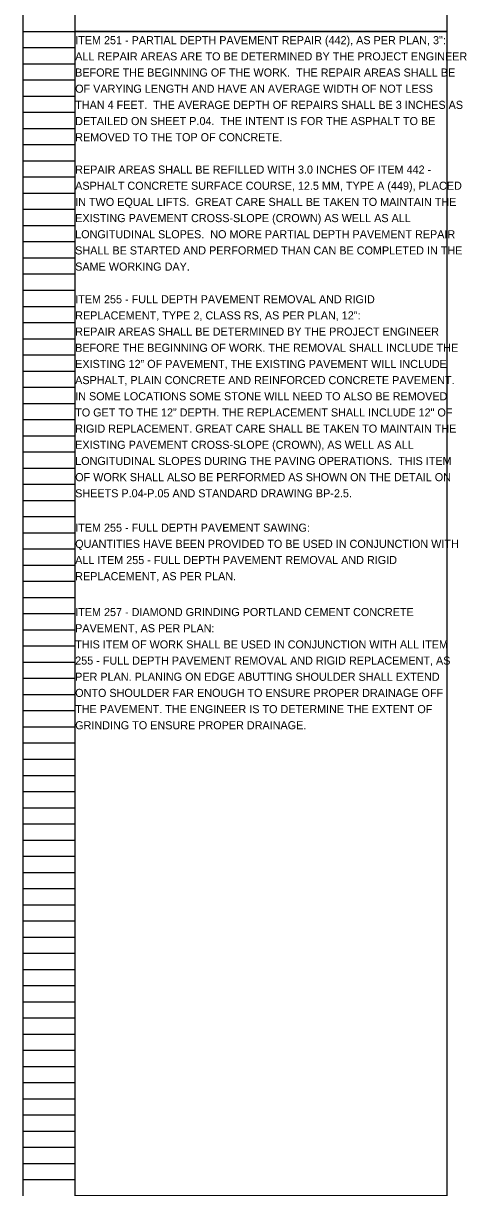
# Model space of a CAD drawing. Extents: x 16463 to 16495, y 5662 to 5823.
# Drawn here: x 16463.05 to 16470.73, y 5783.29 to 5803.45 of the extents above; entities that cross this region are included whole.
import ezdxf

# ---------------------------------------------------------------- set-up
doc = ezdxf.new("R2010")
doc.units = 0
for name, color, linetype in [('Default', 7, 'Continuous'), ('SC_Scratch1', 7, 'Continuous'), ('SH_Data', 7, 'Continuous')]:
    doc.layers.add(name, color=color, linetype=linetype)

msp = doc.modelspace()

# ---------------------------------------------------------------- linework, layer by layer
at = {"layer": 'SC_Scratch1'}
for points in [[(16463.949, 5823.472), (16470.389, 5823.472), (16470.389, 5803.312), (16463.949, 5803.312)], [(16463.949, 5803.312), (16470.389, 5803.312), (16470.389, 5783.152), (16463.949, 5783.152)]]:
    msp.add_lwpolyline(points, close=True, dxfattribs=at)
at = {"layer": 'SH_Data'}
for p, q in [((16463.049, 5803.312), (16463.049, 5823.472)), ((16463.949, 5803.312), (16463.949, 5823.472)), ((16463.049, 5783.152), (16463.049, 5803.312)), ((16463.049, 5803.312), (16463.949, 5803.312)), ((16463.049, 5803.312), (16463.949, 5803.312)), ((16463.949, 5783.152), (16463.949, 5803.312)), ((16463.049, 5803.032), (16463.949, 5803.032)), ((16463.049, 5802.752), (16463.949, 5802.752)), ((16463.049, 5802.472), (16463.949, 5802.472)), ((16463.049, 5802.192), (16463.949, 5802.192)), ((16463.049, 5801.912), (16463.949, 5801.912)), ((16463.049, 5801.632), (16463.949, 5801.632)), ((16463.049, 5801.352), (16463.949, 5801.352)), ((16463.049, 5801.072), (16463.949, 5801.072)), ((16463.049, 5800.792), (16463.949, 5800.792)), ((16463.049, 5800.512), (16463.949, 5800.512)), ((16463.049, 5800.232), (16463.949, 5800.232)), ((16463.049, 5799.952), (16463.949, 5799.952)), ((16463.049, 5799.672), (16463.949, 5799.672)), ((16463.049, 5799.392), (16463.949, 5799.392)), ((16463.049, 5799.112), (16463.949, 5799.112)), ((16463.049, 5798.832), (16463.949, 5798.832)), ((16463.049, 5798.552), (16463.949, 5798.552)), ((16463.049, 5798.272), (16463.949, 5798.272)), ((16463.049, 5797.992), (16463.949, 5797.992)), ((16463.049, 5797.712), (16463.949, 5797.712)), ((16463.049, 5797.432), (16463.949, 5797.432)), ((16463.049, 5797.152), (16463.949, 5797.152)), ((16463.049, 5796.872), (16463.949, 5796.872)), ((16463.049, 5796.592), (16463.949, 5796.592)), ((16463.049, 5796.312), (16463.949, 5796.312)), ((16463.049, 5796.032), (16463.949, 5796.032)), ((16463.049, 5795.752), (16463.949, 5795.752)), ((16463.049, 5795.472), (16463.949, 5795.472)), ((16463.049, 5795.192), (16463.949, 5795.192)), ((16463.049, 5794.912), (16463.949, 5794.912)), ((16463.049, 5794.632), (16463.949, 5794.632)), ((16463.049, 5794.352), (16463.949, 5794.352)), ((16463.049, 5794.072), (16463.949, 5794.072)), ((16463.049, 5793.792), (16463.949, 5793.792)), ((16463.049, 5793.512), (16463.949, 5793.512)), ((16463.049, 5793.232), (16463.949, 5793.232)), ((16463.049, 5792.952), (16463.949, 5792.952)), ((16463.049, 5792.672), (16463.949, 5792.672)), ((16463.049, 5792.392), (16463.949, 5792.392)), ((16463.049, 5792.112), (16463.949, 5792.112)), ((16463.049, 5791.832), (16463.949, 5791.832)), ((16463.049, 5791.552), (16463.949, 5791.552)), ((16463.049, 5791.272), (16463.949, 5791.272)), ((16463.049, 5790.992), (16463.949, 5790.992)), ((16463.049, 5790.712), (16463.949, 5790.712)), ((16463.049, 5790.432), (16463.949, 5790.432)), ((16463.049, 5790.152), (16463.949, 5790.152)), ((16463.049, 5789.872), (16463.949, 5789.872)), ((16463.049, 5789.592), (16463.949, 5789.592)), ((16463.049, 5789.312), (16463.949, 5789.312)), ((16463.049, 5789.032), (16463.949, 5789.032)), ((16463.049, 5788.752), (16463.949, 5788.752)), ((16463.049, 5788.472), (16463.949, 5788.472)), ((16463.049, 5788.192), (16463.949, 5788.192)), ((16463.049, 5787.912), (16463.949, 5787.912)), ((16463.049, 5787.632), (16463.949, 5787.632)), ((16463.049, 5787.352), (16463.949, 5787.352)), ((16463.049, 5787.072), (16463.949, 5787.072)), ((16463.049, 5786.792), (16463.949, 5786.792)), ((16463.049, 5786.512), (16463.949, 5786.512)), ((16463.049, 5786.232), (16463.949, 5786.232)), ((16463.049, 5785.952), (16463.949, 5785.952)), ((16463.049, 5785.672), (16463.949, 5785.672)), ((16463.049, 5785.392), (16463.949, 5785.392)), ((16463.049, 5785.112), (16463.949, 5785.112)), ((16463.049, 5784.832), (16463.949, 5784.832)), ((16463.049, 5784.552), (16463.949, 5784.552)), ((16463.049, 5784.272), (16463.949, 5784.272)), ((16463.049, 5783.992), (16463.949, 5783.992)), ((16463.049, 5783.712), (16463.949, 5783.712)), ((16463.049, 5783.432), (16463.949, 5783.432))]:
    msp.add_line(p, q, dxfattribs=at)

# ---------------------------------------------------------------- texts
at = {"layer": 'Default'}
for s, p in [('ITEM 251 - PARTIAL DEPTH PAVEMENT REPAIR (442), AS PER PLAN, 3":', (16463.949, 5803.09)), ('ALL REPAIR AREAS ARE TO BE DETERMINED BY THE PROJECT ENGINEER ', (16463.949, 5802.81)), ('BEFORE THE BEGINNING OF THE WORK.  THE REPAIR AREAS SHALL BE ', (16463.949, 5802.53)), ('OF VARYING LENGTH AND HAVE AN AVERAGE WIDTH OF NOT LESS ', (16463.949, 5802.25)), ('THAN 4 FEET.  THE AVERAGE DEPTH OF REPAIRS SHALL BE 3 INCHES AS ', (16463.949, 5801.97)), ('DETAILED ON SHEET P.04.  THE INTENT IS FOR THE ASPHALT TO BE ', (16463.949, 5801.69)), ('REMOVED TO THE TOP OF CONCRETE.', (16463.949, 5801.41)), ('REPAIR AREAS SHALL BE REFILLED WITH 3.0 INCHES OF ITEM 442 - ', (16463.949, 5800.85)), ('ASPHALT CONCRETE SURFACE COURSE, 12.5 MM, TYPE A (449), PLACED ', (16463.949, 5800.57)), ('IN TWO EQUAL LIFTS.  GREAT CARE SHALL BE TAKEN TO MAINTAIN THE ', (16463.949, 5800.29)), ('EXISTING PAVEMENT CROSS-SLOPE (CROWN) AS WELL AS ALL ', (16463.949, 5800.01)), ('LONGITUDINAL SLOPES.  NO MORE PARTIAL DEPTH PAVEMENT REPAIR ', (16463.949, 5799.73)), ('SHALL BE STARTED AND PERFORMED THAN CAN BE COMPLETED IN THE ', (16463.949, 5799.45)), ('SAME WORKING DAY.', (16463.949, 5799.17)), ('ITEM 255 - FULL DEPTH PAVEMENT REMOVAL AND RIGID ', (16463.949, 5798.605)), ('REPLACEMENT, TYPE 2, CLASS RS, AS PER PLAN, 12":', (16463.949, 5798.325)), ('REPAIR AREAS SHALL BE DETERMINED BY THE PROJECT ENGINEER ', (16463.949, 5798.045)), ('BEFORE THE BEGINNING OF WORK. THE REMOVAL SHALL INCLUDE THE ', (16463.949, 5797.765)), ('EXISTING 12” OF PAVEMENT, THE EXISTING PAVEMENT WILL INCLUDE ', (16463.949, 5797.485)), ('ASPHALT, PLAIN CONCRETE AND REINFORCED CONCRETE PAVEMENT. ', (16463.949, 5797.205)), ('IN SOME LOCATIONS SOME STONE WILL NEED TO ALSO BE REMOVED ', (16463.949, 5796.925)), ('TO GET TO THE 12” DEPTH. THE REPLACEMENT SHALL INCLUDE 12" OF ', (16463.949, 5796.645)), ('RIGID REPLACEMENT. GREAT CARE SHALL BE TAKEN TO MAINTAIN THE ', (16463.949, 5796.365)), ('EXISTING PAVEMENT CROSS-SLOPE (CROWN), AS WELL AS ALL ', (16463.949, 5796.085)), ('LONGITUDINAL SLOPES DURING THE PAVING OPERATIONS.  THIS ITEM ', (16463.949, 5795.805)), ('OF WORK SHALL ALSO BE PERFORMED AS SHOWN ON THE DETAIL ON ', (16463.949, 5795.525)), ('SHEETS P.04-P.05 AND STANDARD DRAWING BP-2.5.', (16463.949, 5795.245)), ('ITEM 255 - FULL DEPTH PAVEMENT SAWING:', (16463.949, 5794.65)), ('QUANTITIES HAVE BEEN PROVIDED TO BE USED IN CONJUNCTION WITH ', (16463.949, 5794.37)), ('ALL ITEM 255 - FULL DEPTH PAVEMENT REMOVAL AND RIGID ', (16463.949, 5794.09)), ('REPLACEMENT, AS PER PLAN. ', (16463.949, 5793.81)), ('ITEM 257 - DIAMOND GRINDING PORTLAND CEMENT CONCRETE ', (16463.949, 5793.189)), ('PAVEMENT, AS PER PLAN:', (16463.949, 5792.909)), ('THIS ITEM OF WORK SHALL BE USED IN CONJUNCTION WITH ALL ITEM ', (16463.949, 5792.629)), ('255 - FULL DEPTH PAVEMENT REMOVAL AND RIGID REPLACEMENT, AS ', (16463.949, 5792.349)), ('PER PLAN. PLANING ON EDGE ABUTTING SHOULDER SHALL EXTEND ', (16463.949, 5792.069)), ('ONTO SHOULDER FAR ENOUGH TO ENSURE PROPER DRAINAGE OFF ', (16463.949, 5791.789)), ('THE PAVEMENT. THE ENGINEER IS TO DETERMINE THE EXTENT OF ', (16463.949, 5791.509)), ('GRINDING TO ENSURE PROPER DRAINAGE.', (16463.949, 5791.229))]:
    msp.add_text(s, height=0.14, dxfattribs=at).set_placement(p)

doc.saveas('drawing.dxf')
